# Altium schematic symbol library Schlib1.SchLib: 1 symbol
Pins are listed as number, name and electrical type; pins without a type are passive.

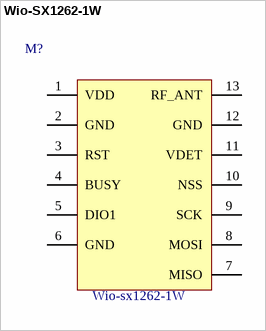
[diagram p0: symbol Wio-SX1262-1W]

## Wio-SX1262-1W
designator M?  value Wio-sx1262-1W  (hidden comment: *)
footprint Wio-SX1262-1W
pins: 1 VDD, 2 GND, 3 RST, 4 BUSY, 5 DIO1, 6 GND, 7 MISO, 8 MOSI, 9 SCK, 10 NSS, 11 VDET, 12 GND, 13 RF_ANT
